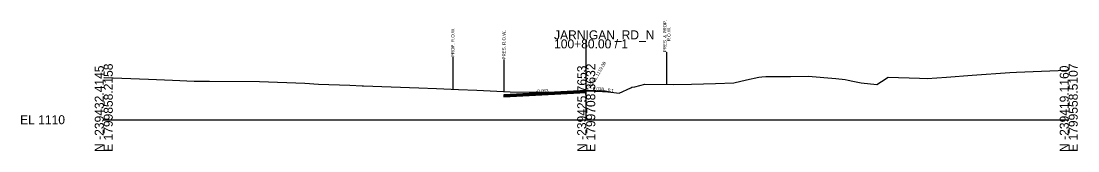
# Model space of a CAD drawing. Extents: x 214513 to 217151, y 214739 to 216780.
# Drawn here: x 214722.7 to 215051.2, y 216238.7 to 216279 of the extents above; entities that cross this region are included whole.
import ezdxf

# ---------------------------------------------------------------- set-up
doc = ezdxf.new("R2010")
doc.units = 0
for name, color, linetype in [('CONCEPT - TRANSPORTATION - Roads Text', 7, 'Continuous'), ('DESIGN - CENTERLINE - Proposed Text', 7, 'Continuous'), ('DESIGN - DRAINAGE - Special Ditches', 7, 'Continuous'), ('DESIGN - EARTHWORK - Shapes', 7, 'Continuous'), ('DESIGN - ROW - Right-of-Way Linework', 7, 'Continuous'), ('DESIGN - TRANSPORTATION - Text', 7, 'Continuous'), ('DESIGN - TYPICAL - Slope Tie Text', 7, 'Continuous'), ('Section', 7, 'Continuous'), ('SURVEY - DTM GRAPHICS - Triangles', 7, 'Continuous'), ('SURVEY - PROPERTY - ROW Lines', 7, 'Continuous'), ('XSCell', 7, 'Continuous')]:
    doc.layers.add(name, color=color, linetype=linetype)

msp = doc.modelspace()

# ---------------------------------------------------------------- linework, layer by layer
at = {"layer": 'DESIGN - DRAINAGE - Special Ditches'}
for points in [[(214898.36, 216257.44), (214872.7, 216256.09), (214872.7, 216256.09), (214872.7, 216255.99), (214898.36, 216257.34), (214898.36, 216257.34), (214898.36, 216257.34), (214898.36, 216257.44), (214898.36, 216257.44)], [(214898.36, 216257.34), (214872.7, 216255.99), (214872.7, 216255.99), (214872.7, 216255.84), (214898.36, 216257.19), (214898.36, 216257.19), (214898.36, 216257.19), (214898.36, 216257.34), (214898.36, 216257.34)], [(214898.36, 216257.19), (214872.7, 216255.84), (214872.7, 216255.84), (214872.7, 216255.51), (214898.36, 216256.86), (214898.36, 216256.86), (214898.36, 216256.86), (214898.36, 216257.19), (214898.36, 216257.19)], [(214904.2, 216257.22), (214898.36, 216257.44), (214898.36, 216257.34), (214898.36, 216257.34), (214904.2, 216257.12), (214904.2, 216257.12), (214904.2, 216257.12), (214904.2, 216257.22), (214904.2, 216257.22)], [(214904.2, 216257.22), (214905.76, 216256.96)]]:
    msp.add_lwpolyline(points, dxfattribs=at)
at = {"layer": 'DESIGN - EARTHWORK - Shapes'}
for p, q in [((214872.7, 216255.84), (214898.36, 216257.19)), ((214872.7, 216255.99), (214893.04, 216257.06)), ((214888.85, 216256.94), (214872.7, 216256.09)), ((214898.36, 216257.34), (214898.36, 216257.32)), ((214898.36, 216257.19), (214898.36, 216257.32)), ((214905.76, 216256.96), (214904.2, 216257.22)), ((214872.7, 216256.09), (214872.7, 216255.99))]:
    msp.add_line(p, q, dxfattribs=at)
for points in [[(214898.36, 216257.19), (214872.7, 216255.84), (214872.7, 216255.51), (214898.36, 216256.86), (214898.36, 216257.19)], [(214893.04, 216257.06), (214872.7, 216255.99), (214872.7, 216255.84)], [(214893.04, 216257.06), (214892.57, 216257.04), (214892.31, 216257.03), (214892.21, 216257.03), (214891.76, 216257), (214888.85, 216256.94)], [(214898.36, 216257.32), (214898.23, 216257.31), (214894.54, 216257.13), (214893.04, 216257.06)], [(214904.2, 216257.22), (214904.2, 216257.12), (214898.36, 216257.34)], [(214898.36, 216257.32), (214898.69, 216257.33), (214899.05, 216257.32), (214903.4, 216257.15), (214904.12, 216257.12), (214904.2, 216257.12), (214904.25, 216257.11), (214904.39, 216257.1), (214905.76, 216256.96)]]:
    msp.add_lwpolyline(points, dxfattribs=at)
at = {"layer": 'DESIGN - ROW - Right-of-Way Linework'}
msp.add_lwpolyline([(214856.88, 216267.82), (214856.88, 216257.82)], dxfattribs=at)
at = {"layer": 'SURVEY - DTM GRAPHICS - Triangles'}
msp.add_lwpolyline([(214748.36, 216261.53), (214748.51, 216261.52), (214762.24, 216261.03), (214769.77, 216260.68), (214776.44, 216260.34), (214781.2, 216260.36), (214796.78, 216260.23), (214810.84, 216259.7), (214815.07, 216259.44), (214824.87, 216259.1), (214828.66, 216258.95), (214829.11, 216258.94), (214846.34, 216258.28), (214851.8, 216258.07), (214858.69, 216257.72), (214864.3, 216257.52), (214874.71, 216257.01), (214884.35, 216256.98), (214887.21, 216256.91), (214891.76, 216257), (214892.21, 216257.03), (214892.31, 216257.03), (214892.57, 216257.04), (214894.54, 216257.13), (214898.23, 216257.31), (214898.69, 216257.33), (214899.05, 216257.32), (214903.4, 216257.15), (214904.12, 216257.12), (214904.2, 216257.12), (214904.25, 216257.11), (214904.39, 216257.1), (214907.81, 216256.76), (214908.59, 216256.67), (214912.23, 216258.33), (214912.58, 216258.5), (214913.47, 216258.63), (214916.58, 216259.46), (214925.57, 216259.31), (214931.06, 216259.39), (214938.5, 216259.66), (214944.2, 216259.85), (214948.14, 216260.73), (214952.04, 216261.58), (214952.99, 216261.66), (214954.22, 216261.79), (214961.88, 216261.86), (214967.36, 216261.89), (214976, 216261.16), (214978.87, 216260.91), (214979.81, 216260.68), (214981.24, 216260.38), (214983.87, 216259.88), (214988.73, 216259.28), (214990.18, 216260.28), (214992.25, 216261.58), (215002.02, 216261.25), (215004.38, 216261.19), (215010.32, 216261.6), (215018.39, 216262.24), (215030.01, 216263.09), (215032.11, 216263.18), (215047.68, 216263.82), (215048.36, 216263.84)], dxfattribs=at)
at = {"layer": 'SURVEY - PROPERTY - ROW Lines'}
for points in [[(214872.77, 216267.11), (214872.77, 216257.11)], [(214923.3, 216269.35), (214923.3, 216259.35)]]:
    msp.add_lwpolyline(points, dxfattribs=at)
at = {"layer": 'XSCell'}
for p, q in [((214898.36, 216248.36), (214898.36, 216273.36)), ((214748.36, 216248.36), (214898.36, 216248.36)), ((214898.36, 216248.36), (215048.36, 216248.36))]:
    msp.add_line(p, q, dxfattribs=at)

# ---------------------------------------------------------------- texts
at = {"layer": 'CONCEPT - TRANSPORTATION - Roads Text'}
for s, rotation, p in [('-0.053', 3.0128, (214882.72, 216256.72)), ('0.038', 357.8134, (214900.34, 216257.52))]:
    msp.add_text(s, height=1, rotation=rotation, dxfattribs=at).set_placement(p)
at = {"layer": 'DESIGN - CENTERLINE - Proposed Text'}
msp.add_text('FG EL.1119.08', height=1, rotation=60, dxfattribs=at).set_placement((214899.86, 216257.94))
at = {"layer": 'DESIGN - TRANSPORTATION - Text'}
for s, p in [('PROP. R.O.W.', (214857.38, 216267.82)), ('PRES. & PROP. ', (214923.3, 216269.35)), ('R.O.W.', (214924.55, 216272.77)), ('PRES. R.O.W.', (214873.27, 216267.11))]:
    msp.add_text(s, height=1, rotation=90, dxfattribs=at).set_placement(p)
at = {"layer": 'DESIGN - TYPICAL - Slope Tie Text'}
msp.add_text('6:1', height=1, rotation=350.5377, dxfattribs=at).set_placement((214904.99, 216257.19))
at = {"layer": 'Section'}
msp.add_text('-', height=0.0001, dxfattribs=at).set_placement((214748.36, 216248.36))
at = {"layer": 'XSCell'}
for s, p in [('JARNIGAN_RD_N', (214888.36, 216273.36)), ('100+80.00 / 1', (214888.36, 216270.56)), ('EL 1110', (214722.36, 216246.96))]:
    msp.add_text(s, height=2.8, dxfattribs=at).set_placement(p)
for s, p in [('N -239432.4145', (214748.36, 216238.36)), ('E 1799858.2158', (214751.16, 216238.36)), ('N -239425.7653', (214898.36, 216238.36)), ('E 1799708.3632', (214901.16, 216238.36)), ('N -239419.1160', (215048.36, 216238.36)), ('E 1799558.5107', (215051.16, 216238.36))]:
    msp.add_text(s, height=2.8, rotation=90, dxfattribs=at).set_placement(p)

doc.saveas('drawing.dxf')
